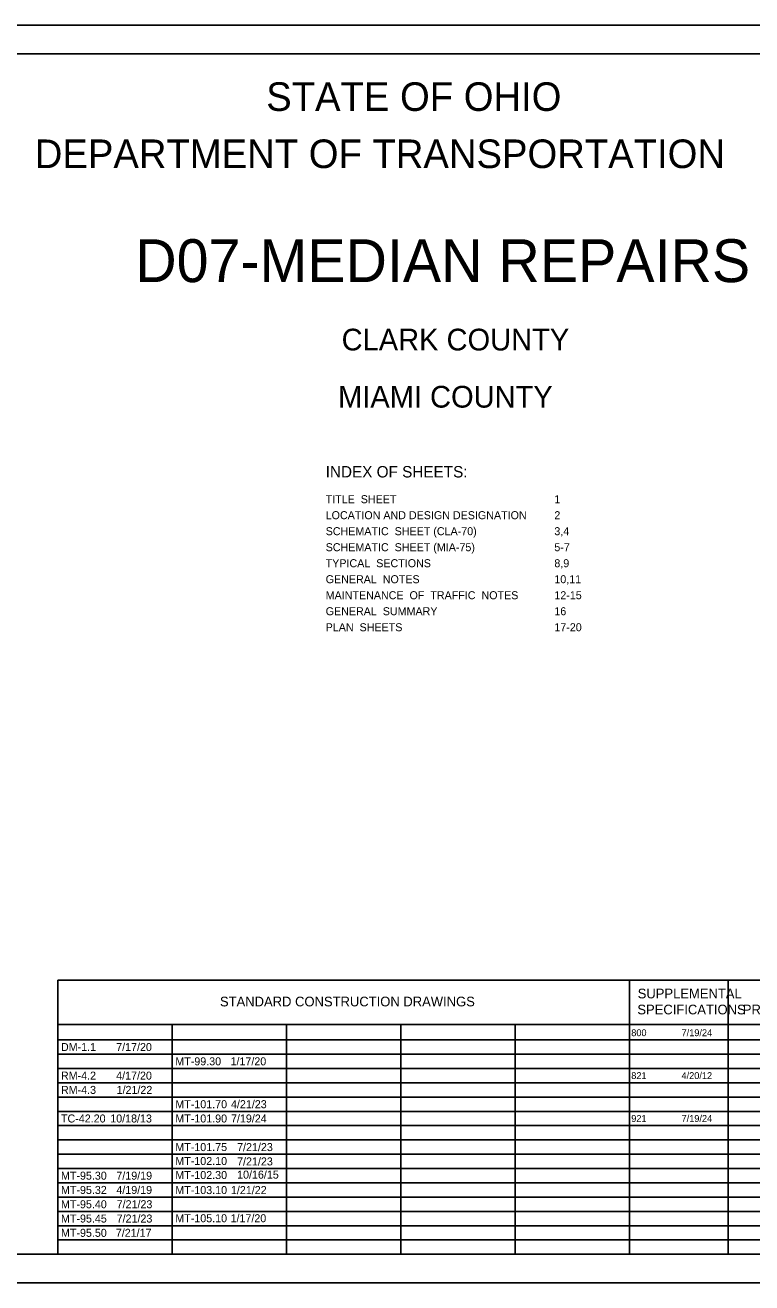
# Model space of a CAD drawing. Extents: x 0 to 34, y 0 to 22.
# Drawn here: x 9.58 to 22.29, y 0 to 22 of the extents above; entities that cross this region are included whole.
import ezdxf

# ---------------------------------------------------------------- set-up
doc = ezdxf.new("R2010")
doc.units = 0
for name, color, linetype in [('SH_Border', 7, 'Continuous'), ('SH_Cut_Line', 7, 'Continuous'), ('SH_Data', 7, 'Continuous'), ('SH_Text', 7, 'Continuous')]:
    doc.layers.add(name, color=color, linetype=linetype)

msp = doc.modelspace()

# ---------------------------------------------------------------- linework, layer by layer
at = {"layer": 'SH_Border'}
msp.add_lwpolyline([(1.5, 21.5), (33.5, 21.5), (33.5, 0.5), (1.5, 0.5)], close=True, dxfattribs=at)
at = {"layer": 'SH_Cut_Line'}
msp.add_lwpolyline([(0, 0), (34, 0), (34, 22), (0, 22)], close=True, dxfattribs=at)
at = {"layer": 'SH_Data'}
for p, q in [((10.15, 5.292), (23.6, 5.292)), ((10.15, 0.5), (10.15, 5.292)), ((20.15, 0.5), (20.15, 5.292)), ((21.875, 0.5), (21.875, 5.292)), ((10.15, 4.521), (23.6, 4.521)), ((12.15, 0.5), (12.15, 4.521)), ((14.15, 0.5), (14.15, 4.521)), ((16.15, 0.5), (16.15, 4.521)), ((18.15, 0.5), (18.15, 4.521)), ((10.15, 4.25), (23.6, 4.25)), ((10.15, 4), (23.6, 4)), ((10.15, 3.75), (23.6, 3.75)), ((10.15, 3.5), (23.6, 3.5)), ((10.15, 3.25), (23.6, 3.25)), ((10.15, 3), (23.6, 3)), ((10.15, 2.75), (23.6, 2.75)), ((10.15, 2.5), (23.6, 2.5)), ((10.15, 2.25), (23.6, 2.25)), ((10.15, 2), (23.6, 2)), ((10.15, 1.75), (23.6, 1.75)), ((10.15, 1.5), (23.6, 1.5)), ((10.15, 1.25), (23.6, 1.25)), ((10.15, 1), (23.6, 1)), ((10.15, 0.75), (23.6, 0.75))]:
    msp.add_line(p, q, dxfattribs=at)

# ---------------------------------------------------------------- texts
at = {"layer": 'SH_Text'}
for s, height, p in [('STATE OF OHIO', 0.5, (13.795, 20.5)), ('DEPARTMENT OF TRANSPORTATION', 0.5, (9.747, 19.5)), ('D07-MEDIAN REPAIRS', 0.75, (11.504, 17.505)), ('CLARK COUNTY', 0.38, (15.114, 16.31)), ('MIAMI COUNTY', 0.38, (15.052, 15.31)), ('INDEX OF SHEETS:', 0.2, (14.835, 14.088)), ('TITLE  SHEET', 0.14, (14.835, 13.638)), ('1', 0.14, (18.835, 13.638)), ('LOCATION AND DESIGN DESIGNATION', 0.14, (14.835, 13.358)), ('2', 0.14, (18.835, 13.358)), ('SCHEMATIC  SHEET (CLA-70)', 0.14, (14.835, 13.078)), ('3,4', 0.14, (18.835, 13.078)), ('SCHEMATIC  SHEET (MIA-75)', 0.14, (14.835, 12.798)), ('5-7', 0.14, (18.835, 12.798)), ('TYPICAL  SECTIONS', 0.14, (14.835, 12.518)), ('8,9', 0.14, (18.835, 12.518)), ('GENERAL  NOTES', 0.14, (14.835, 12.238)), ('10,11', 0.14, (18.835, 12.238)), ('MAINTENANCE  OF  TRAFFIC  NOTES', 0.14, (14.835, 11.958)), ('12-15 ', 0.14, (18.835, 11.958)), ('GENERAL  SUMMARY', 0.14, (14.835, 11.678)), ('16', 0.14, (18.835, 11.678)), ('PLAN  SHEETS', 0.14, (14.835, 11.398)), ('17-20', 0.14, (18.835, 11.398)), ('SUPPLEMENTAL', 0.17, (20.293, 4.976)), ('STANDARD CONSTRUCTION DRAWINGS', 0.17, (12.986, 4.836)), ('SPECIFICATIONS', 0.17, (20.287, 4.696)), ('PROVISIONS', 0.17, (22.132, 4.696)), ('800', 0.12, (20.18, 4.315)), ('7/19/24', 0.12, (21.06, 4.315)), ('DM-1.1', 0.14, (10.205, 4.055)), ('7/17/20', 0.14, (11.171, 4.055)), ('MT-99.30', 0.14, (12.205, 3.805)), ('1/17/20', 0.14, (13.171, 3.805)), ('RM-4.2', 0.14, (10.205, 3.555)), ('4/17/20', 0.14, (11.171, 3.555)), ('821', 0.12, (20.18, 3.565)), ('4/20/12', 0.12, (21.059, 3.565)), ('RM-4.3', 0.14, (10.205, 3.305)), ('1/21/22', 0.14, (11.178, 3.305)), ('MT-101.70', 0.14, (12.205, 3.055)), ('4/21/23', 0.14, (13.179, 3.055)), ('TC-42.20', 0.14, (10.205, 2.805)), ('10/18/13', 0.14, (11.067, 2.805)), ('MT-101.90', 0.14, (12.205, 2.805)), ('7/19/24', 0.14, (13.179, 2.805)), ('921', 0.12, (20.18, 2.815)), ('7/19/24', 0.12, (21.06, 2.815)), ('MT-101.75', 0.14, (12.205, 2.305)), ('7/21/23', 0.14, (13.286, 2.305)), ('MT-102.10', 0.14, (12.205, 2.061)), ('7/21/23', 0.14, (13.286, 2.054)), ('MT-95.30', 0.14, (10.205, 1.805)), ('7/19/19', 0.14, (11.174, 1.805)), ('MT-102.30', 0.14, (12.205, 1.816)), ('10/16/15', 0.14, (13.286, 1.823)), ('MT-95.32', 0.14, (10.205, 1.555)), ('4/19/19', 0.14, (11.174, 1.555)), ('MT-103.10', 0.14, (12.205, 1.553)), ('1/21/22', 0.14, (13.178, 1.553)), ('MT-95.40', 0.14, (10.205, 1.305)), ('7/21/23', 0.14, (11.179, 1.305)), ('MT-95.45', 0.14, (10.205, 1.055)), ('7/21/23', 0.14, (11.179, 1.055)), ('MT-105.10', 0.14, (12.205, 1.06)), ('1/17/20', 0.14, (13.171, 1.06)), ('MT-95.50', 0.14, (10.205, 0.805)), ('7/21/17', 0.14, (11.164, 0.805))]:
    msp.add_text(s, height=height, dxfattribs=at).set_placement(p)

doc.saveas('drawing.dxf')
